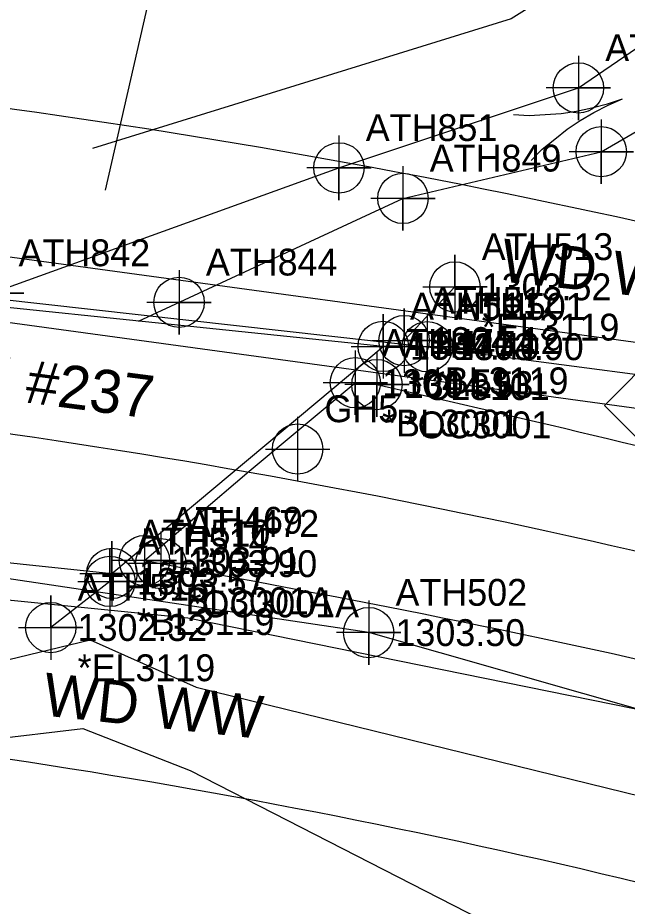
# Model space of a CAD drawing. Extents: x 1234385 to 1237843, y 694759 to 696635.
# Drawn here: x 1234956.3 to 1235013.1, y 695272.7 to 695355.5 of the extents above; entities that cross this region are included whole.
import ezdxf

# ---------------------------------------------------------------- set-up
doc = ezdxf.new("R2010")
doc.units = 0
for name, color, linetype in [('Cogo Default Point CELL', 7, 'Continuous'), ('COGO Default Point Number', 7, 'Continuous'), ('CTL Secondary Horizontal and Vertical CELL', 7, 'Continuous'), ('Exist DTM Drainline Cogo Number', 7, 'Continuous'), ('Exist DTM Drainline Cogo Point CELL', 7, 'Continuous'), ('Exist Guardrail', 7, 'Continuous'), ('Exist Guardrail Cogo Elevation', 7, 'Continuous'), ('Exist Guardrail Cogo Number', 7, 'Continuous'), ('Exist Guardrail Cogo Point CELL', 7, 'Continuous'), ('Exist Horizontal Alignment', 7, 'Continuous'), ('Exist Hydro Jurisdictional Stream or Body of Water', 7, 'Continuous'), ('Exist Hydro Stream Flow Arrow CELL', 7, 'Continuous'), ('Exist Right of Way Line', 7, 'Continuous'), ('Exist Roads EOP', 7, 'Continuous'), ('Exist Roads EOP Cogo Comment', 7, 'Continuous'), ('Exist Roads EOP Cogo Elevation', 7, 'Continuous'), ('Exist Roads EOP Cogo Number', 7, 'Continuous'), ('Exist Roads EOP Cogo Point CELL', 7, 'Continuous'), ('Exist Structure Major Bridge WW', 7, 'Continuous'), ('Exist Structure Major Bridge WW Cogo Comment', 7, 'Continuous'), ('Exist Structure Major Bridge WW Cogo Elevation', 7, 'Continuous'), ('Exist Structure Major Bridge WW Cogo Number', 7, 'Continuous'), ('Exist Structure Major Bridge WW Cogo Point CELL', 7, 'Continuous'), ('Exist Structure Major Bridge WW Text', 7, 'Continuous'), ('Exist Structure Major Deck Tunnel Box Culvert', 7, 'Continuous'), ('Exist Structure Major Deck Tunnel Box Culvert Cogo Comment', 7, 'Continuous'), ('Exist Structure Major Deck Tunnel Box Culvert Cogo Elevation', 7, 'Continuous'), ('Exist Structure Major Deck Tunnel Box Culvert Cogo Number', 7, 'Continuous'), ('Exist Structure Major Deck Tunnel Box Culvert Cogo Point CELL', 7, 'Continuous'), ('Exist Structure Major Deck Tunnel Box Culvert Text', 7, 'Continuous'), ('Exist Utilities Telephone UG Cable SUE LOS C', 7, 'Continuous'), ('Exist Utilities Water UG Line SUE LOS C', 7, 'Continuous'), ('Exist Vegetation Woods Line', 7, 'Continuous')]:
    doc.layers.add(name, color=color, linetype=linetype)

msp = doc.modelspace()

# ---------------------------------------------------------------- linework, layer by layer
at = {"layer": 'Cogo Default Point CELL'}
for points in [[(1234982.35, 695318.272), (1234982.35, 695315.272)], [(1234982.35, 695318.272), (1234982.35, 695315.272)], [(1234979.35, 695315.272), (1234982.35, 695315.272)], [(1234979.35, 695315.272), (1234982.35, 695315.272)], [(1234982.35, 695315.272), (1234985.35, 695315.272)], [(1234982.35, 695315.272), (1234982.35, 695312.272)], [(1234982.35, 695315.272), (1234985.35, 695315.272)], [(1234982.35, 695315.272), (1234982.35, 695312.272)]]:
    msp.add_lwpolyline(points, dxfattribs=at)
msp.add_circle((1234982.35, 695315.272), 2.344, dxfattribs=at)
msp.add_circle((1234982.35, 695315.272), 2.344, dxfattribs=at)
at = {"layer": 'CTL Secondary Horizontal and Vertical CELL'}
msp.add_lwpolyline([(1235010.943, 695319.337), (1235016.185, 695324.578), (1235021.435, 695319.328), (1235016.193, 695314.086)], close=True, dxfattribs=at)
at = {"layer": 'Exist DTM Drainline Cogo Point CELL'}
for points in [[(1235008.526, 695351.915), (1235008.526, 695345.915), (1235008.526, 695348.915), (1235011.526, 695348.915), (1235005.526, 695348.915)], [(1235008.526, 695351.915), (1235008.526, 695345.915), (1235008.526, 695348.915), (1235011.526, 695348.915), (1235005.526, 695348.915)], [(1235010.649, 695345.979), (1235010.649, 695339.979), (1235010.649, 695342.979), (1235013.649, 695342.979), (1235007.649, 695342.979)], [(1235010.649, 695345.979), (1235010.649, 695339.979), (1235010.649, 695342.979), (1235013.649, 695342.979), (1235007.649, 695342.979)], [(1234986.204, 695344.472), (1234986.204, 695338.472), (1234986.204, 695341.472), (1234989.204, 695341.472), (1234983.204, 695341.472)], [(1234986.204, 695344.472), (1234986.204, 695338.472), (1234986.204, 695341.472), (1234989.204, 695341.472), (1234983.204, 695341.472)], [(1234992.169, 695341.626), (1234992.169, 695335.626), (1234992.169, 695338.626), (1234995.169, 695338.626), (1234989.169, 695338.626)], [(1234992.169, 695341.626), (1234992.169, 695335.626), (1234992.169, 695338.626), (1234995.169, 695338.626), (1234989.169, 695338.626)], [(1234953.845, 695332.807), (1234953.845, 695326.807), (1234953.845, 695329.807), (1234956.845, 695329.807), (1234950.845, 695329.807)], [(1234953.845, 695332.807), (1234953.845, 695326.807), (1234953.845, 695329.807), (1234956.845, 695329.807), (1234950.845, 695329.807)], [(1234971.304, 695331.94), (1234971.304, 695325.94), (1234971.304, 695328.94), (1234974.304, 695328.94), (1234968.304, 695328.94)], [(1234971.304, 695331.94), (1234971.304, 695325.94), (1234971.304, 695328.94), (1234974.304, 695328.94), (1234968.304, 695328.94)]]:
    msp.add_lwpolyline(points, dxfattribs=at)
for centre in [(1235008.526, 695348.915), (1235008.526, 695348.915), (1235010.649, 695342.979), (1235010.649, 695342.979), (1234986.204, 695341.472), (1234986.204, 695341.472), (1234992.169, 695338.626), (1234992.169, 695338.626), (1234971.304, 695328.94), (1234971.304, 695328.94)]:
    msp.add_circle(centre, 2.344, dxfattribs=at)
at = {"layer": 'Exist Guardrail'}
for points in [[(1234874.322, 695339.33), (1234931.905, 695331.781), (1234994.435, 695324.804), (1235051.136, 695317.337)], [(1235022.224, 695288.711), (1234988.975, 695298.165), (1234930.412, 695306.902), (1234872.352, 695311.994), (1234846.06, 695313.319)]]:
    msp.add_lwpolyline(points, dxfattribs=at)
at = {"layer": 'Exist Guardrail Cogo Point CELL'}
for points in [[(1234994.435, 695327.804), (1234994.435, 695321.804), (1234994.435, 695324.804), (1234997.435, 695324.804), (1234991.435, 695324.804)], [(1234994.435, 695327.804), (1234994.435, 695321.804), (1234994.435, 695324.804), (1234997.435, 695324.804), (1234991.435, 695324.804)], [(1234988.975, 695301.165), (1234988.975, 695295.165), (1234988.975, 695298.165), (1234991.975, 695298.165), (1234985.975, 695298.165)], [(1234988.975, 695301.165), (1234988.975, 695295.165), (1234988.975, 695298.165), (1234991.975, 695298.165), (1234985.975, 695298.165)]]:
    msp.add_lwpolyline(points, dxfattribs=at)
for centre in [(1234994.435, 695324.804), (1234994.435, 695324.804), (1234988.975, 695298.165), (1234988.975, 695298.165)]:
    msp.add_circle(centre, 2.344, dxfattribs=at)
at = {"layer": 'Exist Horizontal Alignment'}
msp.add_arc((1234852.87, 694607.879), 716.197, 74.437648, 84.817295, dxfattribs=at)
at = {"layer": 'Exist Hydro Jurisdictional Stream or Body of Water'}
msp.add_line((1234952.851, 695295.033), (1234963.03, 695297.482), dxfattribs=at)
for points in [[(1234951.253, 695328.873), (1234986.204, 695341.472), (1235008.526, 695348.915), (1235037.336, 695368.653), (1235069.491, 695383.302), (1235088.448, 695400.861)], [(1234967.536, 695327.191), (1234992.169, 695338.626), (1235010.649, 695342.979), (1235043.523, 695362.073), (1235076.562, 695377.561), (1235094.01, 695394.044)], [(1234963.03, 695297.482), (1234972.886, 695293.093), (1235024.437, 695280.431)], [(1234944.112, 695289.587), (1234953.373, 695288.163), (1234962.335, 695289.234), (1234972.332, 695285.316), (1235018.754, 695261.568)]]:
    msp.add_lwpolyline(points, dxfattribs=at)
at = {"layer": 'Exist Hydro Stream Flow Arrow CELL'}
msp.add_line((1235007.963, 695346.101), (1235007.963, 695346.101), dxfattribs=at)
for points in [[(1235002.475, 695346.434), (1235003.939, 695346.356), (1235005.435, 695346.438), (1235006.91, 695346.539), (1235008.34, 695346.756), (1235009.79, 695347.061), (1235011.236, 695347.446), (1235012.628, 695347.903)], [(1235004.123, 695342.166), (1235005.155, 695343.208), (1235006.317, 695344.153), (1235007.477, 695345.07), (1235008.682, 695345.87), (1235009.961, 695346.618), (1235011.29, 695347.306), (1235012.628, 695347.903)]]:
    msp.add_lwpolyline(points, dxfattribs=at)
at = {"layer": 'Exist Right of Way Line'}
for radius in [746.197, 686.197]:
    msp.add_arc((1234852.87, 694607.879), radius, 74.437648, 84.817295, dxfattribs=at)
at = {"layer": 'Exist Roads EOP'}
for p, q in [((1234987.73, 695321.443), (1234989.744, 695321.275)), ((1234968.075, 695304.88), (1234969.592, 695304.589))]:
    msp.add_line(p, q, dxfattribs=at)
msp.add_lwpolyline([(1234968.075, 695304.88), (1234977.842, 695313.219), (1234987.73, 695321.443)], dxfattribs=at)
for points in [[(1234989.744, 695321.275), (1235032.632, 695310.758), (1235082.97, 695294.625), (1235134.247, 695274.482), (1235183.928, 695250.955), (1235232.115, 695225.68)], [(1234969.592, 695304.589), (1235025.451, 695292.964), (1235076.313, 695277.193), (1235126.218, 695256.569), (1235174.523, 695234.324), (1235222.247, 695208.988)]]:
    msp.add_spline(points, degree=3, dxfattribs=at)
at = {"layer": 'Exist Roads EOP Cogo Point CELL'}
for points in [[(1234987.73, 695324.443), (1234987.73, 695318.443), (1234987.73, 695321.443), (1234990.73, 695321.443), (1234984.73, 695321.443)], [(1234989.744, 695324.275), (1234989.744, 695318.275), (1234989.744, 695321.275), (1234992.744, 695321.275), (1234986.744, 695321.275)], [(1234968.075, 695307.88), (1234968.075, 695301.88), (1234968.075, 695304.88), (1234971.075, 695304.88), (1234965.075, 695304.88)], [(1234969.592, 695307.589), (1234969.592, 695301.589), (1234969.592, 695304.589), (1234972.592, 695304.589), (1234966.592, 695304.589)]]:
    msp.add_lwpolyline(points, dxfattribs=at)
for centre in [(1234987.73, 695321.443), (1234989.744, 695321.275), (1234968.075, 695304.88), (1234969.592, 695304.589)]:
    msp.add_circle(centre, 2.344, dxfattribs=at)
at = {"layer": 'Exist Structure Major Bridge WW'}
for p, q in [((1234992.275, 695325.377), (1234997.012, 695330.381)), ((1234992.275, 695325.377), (1234997.012, 695330.381)), ((1234964.862, 695302.939), (1234959.346, 695298.638)), ((1234964.862, 695302.939), (1234959.346, 695298.638))]:
    msp.add_line(p, q, dxfattribs=at)
at = {"layer": 'Exist Structure Major Bridge WW Cogo Point CELL'}
for points in [[(1234994.012, 695330.381), (1235000.012, 695330.381), (1234997.012, 695330.381), (1234997.012, 695333.381), (1234997.012, 695327.381)], [(1234994.012, 695330.381), (1235000.012, 695330.381), (1234997.012, 695330.381), (1234997.012, 695333.381), (1234997.012, 695327.381)], [(1234989.275, 695325.377), (1234995.275, 695325.377), (1234992.275, 695325.377), (1234992.275, 695328.377), (1234992.275, 695322.377)], [(1234989.275, 695325.377), (1234995.275, 695325.377), (1234992.275, 695325.377), (1234992.275, 695328.377), (1234992.275, 695322.377)], [(1234961.862, 695302.939), (1234967.862, 695302.939), (1234964.862, 695302.939), (1234964.862, 695305.939), (1234964.862, 695299.939)], [(1234961.862, 695302.939), (1234967.862, 695302.939), (1234964.862, 695302.939), (1234964.862, 695305.939), (1234964.862, 695299.939)], [(1234956.346, 695298.638), (1234962.346, 695298.638), (1234959.346, 695298.638), (1234959.346, 695301.638), (1234959.346, 695295.638)], [(1234956.346, 695298.638), (1234962.346, 695298.638), (1234959.346, 695298.638), (1234959.346, 695301.638), (1234959.346, 695295.638)]]:
    msp.add_lwpolyline(points, dxfattribs=at)
for centre in [(1234997.012, 695330.381), (1234997.012, 695330.381), (1234992.275, 695325.377), (1234992.275, 695325.377), (1234964.862, 695302.939), (1234964.862, 695302.939), (1234959.346, 695298.638), (1234959.346, 695298.638)]:
    msp.add_circle(centre, 2.344, dxfattribs=at)
at = {"layer": 'Exist Structure Major Deck Tunnel Box Culvert'}
msp.add_lwpolyline([(1234932.242, 695330.836), (1234906.381, 695309.848), (1234965.045, 695303.686), (1234990.33, 695324.837), (1234932.242, 695330.836)], dxfattribs=at)
at = {"layer": 'Exist Structure Major Deck Tunnel Box Culvert Cogo Point CELL'}
for points in [[(1234987.33, 695324.837), (1234993.33, 695324.837), (1234990.33, 695324.837), (1234990.33, 695327.837), (1234990.33, 695321.837)], [(1234987.33, 695324.837), (1234993.33, 695324.837), (1234990.33, 695324.837), (1234990.33, 695327.837), (1234990.33, 695321.837)], [(1234962.045, 695303.686), (1234968.045, 695303.686), (1234965.045, 695303.686), (1234965.045, 695306.686), (1234965.045, 695300.686)], [(1234962.045, 695303.686), (1234968.045, 695303.686), (1234965.045, 695303.686), (1234965.045, 695306.686), (1234965.045, 695300.686)]]:
    msp.add_lwpolyline(points, dxfattribs=at)
for centre in [(1234990.33, 695324.837), (1234990.33, 695324.837), (1234965.045, 695303.686), (1234965.045, 695303.686)]:
    msp.add_circle(centre, 2.344, dxfattribs=at)
at = {"layer": 'Exist Utilities Telephone UG Cable SUE LOS C'}
for points in [[(1234612.85, 695374.355), (1234612.119, 695364.285), (1234648.821, 695358.531), (1234708.167, 695353.722), (1234769.772, 695349.962), (1234824.928, 695344.089), (1234870.543, 695338.673), (1235040.507, 695315.445), (1235102.265, 695295.191), (1235205.889, 695246.165), (1235265.515, 695210.169), (1235282.655, 695201.724), (1235295.315, 695230.287)], [(1234556.879, 695335.534), (1234556.739, 695340.721), (1234570.651, 695340.511), (1234623.538, 695336.024), (1234680.233, 695326.896), (1234743.004, 695322.741), (1234798.613, 695317.565), (1234871.043, 695309.649), (1234972.116, 695299.536), (1235029.46, 695287.899), (1235091.912, 695268.263), (1235135.265, 695250.065), (1235195.375, 695220.093), (1235241.543, 695194.865), (1235279.054, 695173.584)]]:
    msp.add_lwpolyline(points, dxfattribs=at)
at = {"layer": 'Exist Utilities Water UG Line SUE LOS C'}
msp.add_line((1234858.298, 695346.432), (1235062.37, 695318.599), dxfattribs=at)
at = {"layer": 'Exist Vegetation Woods Line'}
for points in [[(1234964.439, 695339.394), (1234976.242, 695390.982), (1234988.396, 695402.183), (1235059.083, 695421.385), (1235076.355, 695440.026)], [(1235090.226, 695410.415), (1235054.083, 695384.493), (1235027.855, 695371.372), (1235002.267, 695355.371), (1234963.234, 695343.283)]]:
    msp.add_lwpolyline(points, dxfattribs=at)

# ---------------------------------------------------------------- texts
at = {"layer": 'COGO Default Point Number'}
msp.add_text('GH5', height=2.5, dxfattribs=at).set_placement((1234984.85, 695317.772))
at = {"layer": 'Exist DTM Drainline Cogo Number'}
for s, p in [('ATH859', (1235011.026, 695351.415)), ('ATH859', (1235011.026, 695351.415)), ('ATH851', (1234988.704, 695343.972)), ('ATH851', (1234988.704, 695343.972)), ('ATH849', (1234994.669, 695341.126)), ('ATH849', (1234994.669, 695341.126)), ('ATH842', (1234956.345, 695332.307)), ('ATH842', (1234956.345, 695332.307)), ('ATH844', (1234973.804, 695331.44)), ('ATH844', (1234973.804, 695331.44))]:
    msp.add_text(s, height=2.5, dxfattribs=at).set_placement(p)
at = {"layer": 'Exist Guardrail Cogo Elevation'}
for s, p in [('1303.90', (1234996.935, 695323.554)), ('1303.90', (1234996.935, 695323.554)), ('1303.50', (1234991.475, 695296.915)), ('1303.50', (1234991.475, 695296.915))]:
    msp.add_text(s, height=2.5, dxfattribs=at).set_placement(p)
at = {"layer": 'Exist Guardrail Cogo Number'}
for s, p in [('ATH501', (1234996.935, 695327.304)), ('ATH501', (1234996.935, 695327.304)), ('ATH502', (1234991.475, 695300.665)), ('ATH502', (1234991.475, 695300.665))]:
    msp.add_text(s, height=2.5, dxfattribs=at).set_placement(p)
at = {"layer": 'Exist Roads EOP Cogo Comment'}
for s, p in [('*BL3001', (1234990.23, 695316.443)), ('*OC3001', (1234992.244, 695316.275)), ('*BL3001A', (1234970.575, 695299.88)), ('*OC3001A', (1234972.092, 695299.589))]:
    msp.add_text(s, height=2.5, dxfattribs=at).set_placement(p)
at = {"layer": 'Exist Roads EOP Cogo Elevation'}
for s, p in [('1304.59', (1234990.23, 695320.193)), ('1304.53', (1234992.244, 695320.025)), ('1303.91', (1234970.575, 695303.63)), ('1303.90', (1234972.092, 695303.339))]:
    msp.add_text(s, height=2.5, dxfattribs=at).set_placement(p)
at = {"layer": 'Exist Roads EOP Cogo Number'}
for s, p in [('ATH471', (1234990.23, 695323.943)), ('ATH474', (1234992.244, 695323.775)), ('ATH469', (1234970.575, 695307.38)), ('ATH472', (1234972.092, 695307.089))]:
    msp.add_text(s, height=2.5, dxfattribs=at).set_placement(p)
at = {"layer": 'Exist Structure Major Bridge WW Cogo Comment'}
for s, p in [('*EL3119', (1234999.512, 695325.381)), ('*EL3119', (1234999.512, 695325.381)), ('*BL3119', (1234994.775, 695320.377)), ('*BL3119', (1234994.775, 695320.377)), ('*BL3119', (1234967.362, 695297.939)), ('*BL3119', (1234967.362, 695297.939)), ('*EL3119', (1234961.846, 695293.638)), ('*EL3119', (1234961.846, 695293.638))]:
    msp.add_text(s, height=2.5, dxfattribs=at).set_placement(p)
at = {"layer": 'Exist Structure Major Bridge WW Cogo Elevation'}
for s, p in [('1303.52', (1234999.512, 695329.131)), ('1303.52', (1234999.512, 695329.131)), ('1304.12', (1234994.775, 695324.127)), ('1304.12', (1234994.775, 695324.127)), ('1303.57', (1234967.362, 695301.689)), ('1303.57', (1234967.362, 695301.689)), ('1302.32', (1234961.846, 695297.388)), ('1302.32', (1234961.846, 695297.388))]:
    msp.add_text(s, height=2.5, dxfattribs=at).set_placement(p)
at = {"layer": 'Exist Structure Major Bridge WW Cogo Number'}
for s, p in [('ATH513', (1234999.512, 695332.881)), ('ATH513', (1234999.512, 695332.881)), ('ATH512', (1234994.775, 695327.877)), ('ATH512', (1234994.775, 695327.877)), ('ATH514', (1234967.362, 695305.439)), ('ATH514', (1234967.362, 695305.439)), ('ATH515', (1234961.846, 695301.138)), ('ATH515', (1234961.846, 695301.138))]:
    msp.add_text(s, height=2.5, dxfattribs=at).set_placement(p)
at = {"layer": 'Exist Structure Major Bridge WW Text'}
for p in [(1235001.174, 695330.901), (1234958.494, 695290.46)]:
    msp.add_text('WD WW', height=4, rotation=353.83427, dxfattribs=at).set_placement(p)
at = {"layer": 'Exist Structure Major Deck Tunnel Box Culvert Cogo Comment'}
msp.add_text('*CL3101', height=2.5, dxfattribs=at).set_placement((1234992.83, 695319.837))
msp.add_text('*CL3101', height=2.5, dxfattribs=at).set_placement((1234992.83, 695319.837))
at = {"layer": 'Exist Structure Major Deck Tunnel Box Culvert Cogo Elevation'}
for s, p in [('1304.40', (1234992.83, 695323.587)), ('1304.40', (1234992.83, 695323.587)), ('1303.77', (1234967.545, 695302.436)), ('1303.77', (1234967.545, 695302.436))]:
    msp.add_text(s, height=2.5, dxfattribs=at).set_placement(p)
at = {"layer": 'Exist Structure Major Deck Tunnel Box Culvert Cogo Number'}
for s, p in [('ATH511', (1234992.83, 695327.337)), ('ATH511', (1234992.83, 695327.337)), ('ATH510', (1234967.545, 695306.186)), ('ATH510', (1234967.545, 695306.186))]:
    msp.add_text(s, height=2.5, dxfattribs=at).set_placement(p)
at = {"layer": 'Exist Structure Major Deck Tunnel Box Culvert Text'}
msp.add_text('BRIDGE #237', height=4, rotation=352.58135, dxfattribs=at).set_placement((1234935.06, 695322.463))

doc.saveas('drawing.dxf')
